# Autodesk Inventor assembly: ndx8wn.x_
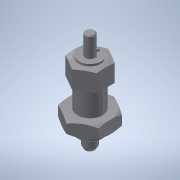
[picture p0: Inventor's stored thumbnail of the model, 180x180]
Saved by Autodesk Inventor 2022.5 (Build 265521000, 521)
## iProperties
Part Number: ndx8wn.x_
Material: 一般
Document SubType Name: Assembly
Designer: ImaoCorp
Sending System: SOLIDWORKS 2017-2017317
MC: AMD64
MC_MODEL: Intel64 Family 6 Model 60 Stepping 3, GenuineIntel
OS: Windows_NT
FRU: Parasolid Version 29.0, build 201,  4-17-2017
FORMAT: text
GUISE: transmit
KEY: ndx8wn
FILE: ndx8wn.x_t
DATE: Wed Sep 04 15:30:26 2019
Author: ImaoCorp
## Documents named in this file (3)
- X:\14_SW2022-Inv2022\00_全2023-1023新製品(TCC)まで\n\ndx8wn\NDX8WN.iam
- X:\14_SW2022-Inv2022\00_全2023-1023新製品(TCC)まで\n\ndx8wn\ndx8wn_01.ipt
- X:\14_SW2022-Inv2022\00_全2023-1023新製品(TCC)まで\n\ndx8wn\ndx8wn_02.ipt
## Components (2 placed, 2 different names)
1. ndx8wn_01
2. ndx8wn_02
